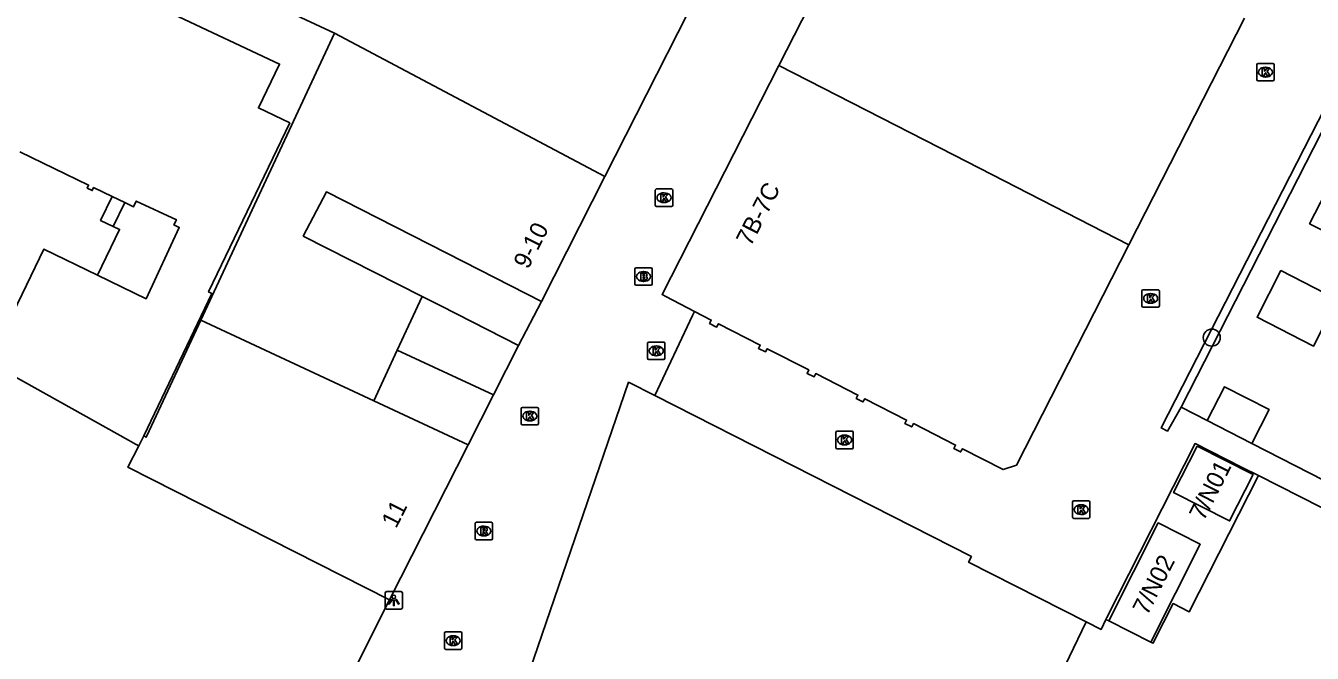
# Model space of a CAD drawing. Extents: x 160356 to 161355, y 381727 to 382845.
# Drawn here: x 160622.2 to 160696, y 382251.7 to 382287.6 of the extents above; entities that cross this region are included whole.
import ezdxf

# ---------------------------------------------------------------- set-up
doc = ezdxf.new("R2010")
doc.units = 0
for name, color, linetype in [('IMGEO_Boom', 7, 'Continuous'), ('IMGEO_Brandkraan', 7, 'Continuous'), ('IMGEO_Haag', 7, 'Continuous'), ('IMGEO_Kolk', 7, 'Continuous'), ('IMGEO_Lichtpunt', 7, 'Continuous'), ('IMGEO_Pand', 7, 'Continuous'), ('IMGEO_Pand_nummerreeks', 7, 'Continuous'), ('IMGEO_Rijbaan_lokaal_open', 7, 'Continuous'), ('IMGEO_Rioolput', 7, 'Continuous'), ('IMGEO_Voetpad_op_trap', 7, 'Continuous'), ('IMGEO_Voetpad_open', 7, 'Continuous')]:
    doc.layers.add(name, color=color, linetype=linetype)

msp = doc.modelspace()

# ---------------------------------------------------------------- linework, layer by layer
at = {"layer": 'IMGEO_Boom'}
msp.add_circle((160690.218, 382269.777), 0.489, dxfattribs=at)
at = {"layer": 'IMGEO_Brandkraan'}
for p, q in [((160657.122, 382272.853), (160657.122, 382273.705)), ((160657.197, 382273.779), (160658.049, 382273.779)), ((160657.61, 382273.559), (160657.635, 382273.559)), ((160658.123, 382273.705), (160658.123, 382272.853)), ((160658.049, 382272.779), (160657.197, 382272.779)), ((160657.633, 382272.999), (160657.608, 382272.999))]:
    msp.add_line(p, q, dxfattribs=at)
for points in [[(160657.122, 382272.853), (160657.122, 382273.705)], [(160657.197, 382273.779), (160658.049, 382273.779)], [(160657.47, 382273.479), (160657.47, 382273.079), (160657.683, 382273.079)], [(160657.701, 382273.479), (160657.47, 382273.479)], [(160658.123, 382273.705), (160658.123, 382272.853)], [(160658.049, 382272.779), (160657.197, 382272.779)], [(160657.649, 382273.398), (160657.595, 382273.398), (160657.595, 382273.322)], [(160657.595, 382273.322), (160657.648, 382273.322)], [(160657.657, 382273.246), (160657.595, 382273.246), (160657.595, 382273.165)], [(160657.595, 382273.165), (160657.657, 382273.165)]]:
    msp.add_lwpolyline(points, dxfattribs=at)
for centre, radius, start, end in [((160657.199, 382273.703), 0.0765, 91.55205, 178.44795), ((160657.199, 382273.703), 0.0765, 91.55205, 178.44795), ((160657.705, 382273.334), 0.145, 59.4692, 91.53667), ((160658.047, 382273.703), 0.0765, 1.55205, 88.44795), ((160658.047, 382273.703), 0.0765, 1.55205, 88.44795), ((160657.199, 382272.855), 0.0765, 181.55205, 268.44795), ((160657.199, 382272.855), 0.0765, 181.55205, 268.44795), ((160657.65, 382273.36), 0.0379, 267.82845, 90.93552), ((160657.658, 382273.205), 0.0404, 269.87594, 90.50774), ((160657.689, 382273.33), 0.251, 268.66757, 293.53466), ((160657.73, 382273.381), 0.0922, 285.51372, 58.15012), ((160657.735, 382273.189), 0.105, 301.31148, 78.98903), ((160658.047, 382272.855), 0.0765, 271.55205, 358.44795), ((160658.047, 382272.855), 0.0765, 271.55205, 358.44795)]:
    msp.add_arc(centre, radius, start, end, dxfattribs=at)
for centre, major_axis, ratio, start_param, end_param in [((160657.609, 382273.279), (-0.387, 0.002), 0.722429, 4.712389, 7.853982), ((160657.634, 382273.279), (-0.39, 0.002), 0.717154, 1.570796, 4.712389)]:
    msp.add_ellipse(centre, major_axis=major_axis, ratio=ratio, start_param=start_param, end_param=end_param, dxfattribs=at)
at = {"layer": 'IMGEO_Haag'}
msp.add_lwpolyline([(160688.461, 382265.787), (160729.098, 382345.248)], dxfattribs=at)
at = {"layer": 'IMGEO_Kolk'}
for p, q in [((160692.796, 382284.567), (160692.796, 382285.419)), ((160692.871, 382285.493), (160693.723, 382285.493)), ((160693.797, 382285.419), (160693.797, 382284.567)), ((160693.307, 382284.713), (160693.282, 382284.713)), ((160693.284, 382285.273), (160693.309, 382285.273)), ((160693.723, 382284.493), (160692.871, 382284.493)), ((160658.297, 382277.37), (160658.297, 382278.222)), ((160658.372, 382278.296), (160659.224, 382278.296)), ((160658.785, 382278.076), (160658.81, 382278.076)), ((160659.298, 382278.222), (160659.298, 382277.37)), ((160659.224, 382277.296), (160658.372, 382277.296)), ((160658.808, 382277.516), (160658.783, 382277.516)), ((160686.212, 382271.599), (160686.212, 382272.451)), ((160686.287, 382272.525), (160687.139, 382272.525)), ((160686.7, 382272.305), (160686.725, 382272.305)), ((160687.213, 382272.451), (160687.213, 382271.599)), ((160687.139, 382271.525), (160686.287, 382271.525)), ((160686.723, 382271.745), (160686.698, 382271.745)), ((160657.851, 382268.593), (160657.851, 382269.445)), ((160657.926, 382269.519), (160658.778, 382269.519)), ((160658.339, 382269.299), (160658.364, 382269.299)), ((160658.852, 382269.445), (160658.852, 382268.593)), ((160658.778, 382268.519), (160657.926, 382268.519)), ((160658.362, 382268.739), (160658.337, 382268.739)), ((160650.596, 382264.856), (160650.596, 382265.708)), ((160650.671, 382265.782), (160651.523, 382265.782)), ((160651.084, 382265.562), (160651.109, 382265.562)), ((160651.597, 382265.708), (160651.597, 382264.856)), ((160651.523, 382264.782), (160650.671, 382264.782)), ((160651.107, 382265.002), (160651.082, 382265.002)), ((160668.655, 382263.485), (160668.655, 382264.337)), ((160668.73, 382264.411), (160669.582, 382264.411)), ((160669.143, 382264.191), (160669.168, 382264.191)), ((160669.656, 382264.337), (160669.656, 382263.485)), ((160669.582, 382263.411), (160668.73, 382263.411)), ((160669.166, 382263.631), (160669.141, 382263.631)), ((160682.222, 382259.495), (160682.222, 382260.347)), ((160682.297, 382260.421), (160683.149, 382260.421)), ((160682.71, 382260.201), (160682.735, 382260.201)), ((160683.223, 382260.347), (160683.223, 382259.495)), ((160682.733, 382259.641), (160682.708, 382259.641)), ((160683.149, 382259.421), (160682.297, 382259.421)), ((160646.203, 382251.987), (160646.203, 382252.839)), ((160646.278, 382252.913), (160647.13, 382252.913)), ((160647.204, 382252.839), (160647.204, 382251.987)), ((160646.714, 382252.133), (160646.689, 382252.133)), ((160646.691, 382252.693), (160646.716, 382252.693)), ((160647.13, 382251.913), (160646.278, 382251.913))]:
    msp.add_line(p, q, dxfattribs=at)
for points in [[(160692.796, 382284.567), (160692.796, 382285.419)], [(160692.871, 382285.493), (160693.723, 382285.493)], [(160693.797, 382285.419), (160693.797, 382284.567)], [(160693.117, 382285.193), (160693.24, 382285.193), (160693.24, 382285.042), (160693.37, 382285.193), (160693.534, 382285.193), (160693.388, 382285.042), (160693.541, 382284.793), (160693.389, 382284.793), (160693.304, 382284.957), (160693.24, 382284.89), (160693.24, 382284.793), (160693.117, 382284.793), (160693.117, 382285.193)], [(160693.723, 382284.493), (160692.871, 382284.493)], [(160658.297, 382277.37), (160658.297, 382278.222)], [(160658.372, 382278.296), (160659.224, 382278.296)], [(160658.618, 382277.996), (160658.741, 382277.996), (160658.741, 382277.845), (160658.871, 382277.996), (160659.035, 382277.996), (160658.889, 382277.845), (160659.042, 382277.596), (160658.89, 382277.596), (160658.805, 382277.76), (160658.741, 382277.693), (160658.741, 382277.596), (160658.618, 382277.596), (160658.618, 382277.996)], [(160659.298, 382278.222), (160659.298, 382277.37)], [(160659.224, 382277.296), (160658.372, 382277.296)], [(160686.212, 382271.599), (160686.212, 382272.451)], [(160686.287, 382272.525), (160687.139, 382272.525)], [(160686.533, 382272.225), (160686.656, 382272.225), (160686.656, 382272.074), (160686.786, 382272.225), (160686.95, 382272.225), (160686.804, 382272.074), (160686.957, 382271.825), (160686.805, 382271.825), (160686.72, 382271.989), (160686.656, 382271.922), (160686.656, 382271.825), (160686.533, 382271.825), (160686.533, 382272.225)], [(160687.213, 382272.451), (160687.213, 382271.599)], [(160687.139, 382271.525), (160686.287, 382271.525)], [(160657.851, 382268.593), (160657.851, 382269.445)], [(160657.926, 382269.519), (160658.778, 382269.519)], [(160658.172, 382269.219), (160658.295, 382269.219), (160658.295, 382269.068), (160658.425, 382269.219), (160658.589, 382269.219), (160658.443, 382269.068), (160658.596, 382268.819), (160658.444, 382268.819), (160658.359, 382268.983), (160658.295, 382268.916), (160658.295, 382268.819), (160658.172, 382268.819), (160658.172, 382269.219)], [(160658.852, 382269.445), (160658.852, 382268.593)], [(160658.778, 382268.519), (160657.926, 382268.519)], [(160650.596, 382264.856), (160650.596, 382265.708)], [(160650.671, 382265.782), (160651.523, 382265.782)], [(160650.917, 382265.482), (160651.04, 382265.482), (160651.04, 382265.331), (160651.17, 382265.482), (160651.334, 382265.482), (160651.188, 382265.331), (160651.341, 382265.082), (160651.189, 382265.082), (160651.104, 382265.246), (160651.04, 382265.179), (160651.04, 382265.082), (160650.917, 382265.082), (160650.917, 382265.482)], [(160651.597, 382265.708), (160651.597, 382264.856)], [(160651.523, 382264.782), (160650.671, 382264.782)], [(160668.655, 382263.485), (160668.655, 382264.337)], [(160668.73, 382264.411), (160669.582, 382264.411)], [(160668.976, 382264.111), (160669.099, 382264.111), (160669.099, 382263.96), (160669.229, 382264.111), (160669.393, 382264.111), (160669.247, 382263.96), (160669.4, 382263.711), (160669.248, 382263.711), (160669.163, 382263.875), (160669.099, 382263.808), (160669.099, 382263.711), (160668.976, 382263.711), (160668.976, 382264.111)], [(160669.656, 382264.337), (160669.656, 382263.485)], [(160669.582, 382263.411), (160668.73, 382263.411)], [(160682.222, 382259.495), (160682.222, 382260.347)], [(160682.297, 382260.421), (160683.149, 382260.421)], [(160683.223, 382260.347), (160683.223, 382259.495)], [(160682.543, 382260.121), (160682.666, 382260.121), (160682.666, 382259.97), (160682.796, 382260.121), (160682.96, 382260.121), (160682.814, 382259.97), (160682.967, 382259.721), (160682.815, 382259.721), (160682.73, 382259.885), (160682.666, 382259.818), (160682.666, 382259.721), (160682.543, 382259.721), (160682.543, 382260.121)], [(160683.149, 382259.421), (160682.297, 382259.421)], [(160646.203, 382251.987), (160646.203, 382252.839)], [(160646.278, 382252.913), (160647.13, 382252.913)], [(160647.204, 382252.839), (160647.204, 382251.987)], [(160646.524, 382252.613), (160646.647, 382252.613), (160646.647, 382252.462), (160646.777, 382252.613), (160646.941, 382252.613), (160646.795, 382252.462), (160646.948, 382252.213), (160646.796, 382252.213), (160646.711, 382252.377), (160646.647, 382252.31), (160646.647, 382252.213), (160646.524, 382252.213), (160646.524, 382252.613)], [(160647.13, 382251.913), (160646.278, 382251.913)]]:
    msp.add_lwpolyline(points, dxfattribs=at)
for centre, start, end in [((160692.873, 382285.417), 91.55205, 178.44795), ((160692.873, 382285.417), 91.55205, 178.44795), ((160693.721, 382285.417), 1.55205, 88.44795), ((160693.721, 382285.417), 1.55205, 88.44795), ((160692.873, 382284.569), 181.55205, 268.44795), ((160692.873, 382284.569), 181.55205, 268.44795), ((160693.721, 382284.569), 271.55205, 358.44795), ((160693.721, 382284.569), 271.55205, 358.44795), ((160658.374, 382278.22), 91.55205, 178.44795), ((160658.374, 382278.22), 91.55205, 178.44795), ((160659.222, 382278.22), 1.55205, 88.44795), ((160659.222, 382278.22), 1.55205, 88.44795), ((160658.374, 382277.372), 181.55205, 268.44795), ((160658.374, 382277.372), 181.55205, 268.44795), ((160659.222, 382277.372), 271.55205, 358.44795), ((160659.222, 382277.372), 271.55205, 358.44795), ((160686.289, 382272.449), 91.55205, 178.44795), ((160686.289, 382272.449), 91.55205, 178.44795), ((160687.137, 382272.449), 1.55205, 88.44795), ((160687.137, 382272.449), 1.55205, 88.44795), ((160686.289, 382271.601), 181.55205, 268.44795), ((160686.289, 382271.601), 181.55205, 268.44795), ((160687.137, 382271.601), 271.55205, 358.44795), ((160687.137, 382271.601), 271.55205, 358.44795), ((160657.928, 382269.443), 91.55205, 178.44795), ((160657.928, 382269.443), 91.55205, 178.44795), ((160658.776, 382269.443), 1.55205, 88.44795), ((160658.776, 382269.443), 1.55205, 88.44795), ((160657.928, 382268.595), 181.55205, 268.44795), ((160657.928, 382268.595), 181.55205, 268.44795), ((160658.776, 382268.595), 271.55205, 358.44795), ((160658.776, 382268.595), 271.55205, 358.44795), ((160650.673, 382265.706), 91.55205, 178.44795), ((160650.673, 382265.706), 91.55205, 178.44795), ((160651.521, 382265.706), 1.55205, 88.44795), ((160651.521, 382265.706), 1.55205, 88.44795), ((160650.673, 382264.858), 181.55205, 268.44795), ((160650.673, 382264.858), 181.55205, 268.44795), ((160651.521, 382264.858), 271.55205, 358.44795), ((160651.521, 382264.858), 271.55205, 358.44795), ((160668.732, 382264.335), 91.55205, 178.44795), ((160668.732, 382264.335), 91.55205, 178.44795), ((160669.58, 382264.335), 1.55205, 88.44795), ((160669.58, 382264.335), 1.55205, 88.44795), ((160668.732, 382263.487), 181.55205, 268.44795), ((160668.732, 382263.487), 181.55205, 268.44795), ((160669.58, 382263.487), 271.55205, 358.44795), ((160669.58, 382263.487), 271.55205, 358.44795), ((160682.299, 382260.345), 91.55205, 178.44795), ((160682.299, 382260.345), 91.55205, 178.44795), ((160683.147, 382260.345), 1.55205, 88.44795), ((160683.147, 382260.345), 1.55205, 88.44795), ((160682.299, 382259.497), 181.55205, 268.44795), ((160682.299, 382259.497), 181.55205, 268.44795), ((160683.147, 382259.497), 271.55205, 358.44795), ((160683.147, 382259.497), 271.55205, 358.44795), ((160646.28, 382252.837), 91.55205, 178.44795), ((160646.28, 382252.837), 91.55205, 178.44795), ((160647.128, 382252.837), 1.55205, 88.44795), ((160647.128, 382252.837), 1.55205, 88.44795), ((160646.28, 382251.989), 181.55205, 268.44795), ((160646.28, 382251.989), 181.55205, 268.44795), ((160647.128, 382251.989), 271.55205, 358.44795), ((160647.128, 382251.989), 271.55205, 358.44795)]:
    msp.add_arc(centre, 0.0765, start, end, dxfattribs=at)
for centre, major_axis, ratio, start_param, end_param in [((160693.283, 382284.993), (-0.387, 0.002), 0.722429, 4.712389, 7.853982), ((160693.308, 382284.993), (-0.39, 0.002), 0.717154, 1.570796, 4.712389), ((160658.784, 382277.796), (-0.387, 0.002), 0.722429, 4.712389, 7.853982), ((160658.809, 382277.796), (-0.39, 0.002), 0.717154, 1.570796, 4.712389), ((160686.699, 382272.025), (-0.387, 0.002), 0.722429, 4.712389, 7.853982), ((160686.724, 382272.025), (-0.39, 0.002), 0.717154, 1.570796, 4.712389), ((160658.338, 382269.019), (-0.387, 0.002), 0.722429, 4.712389, 7.853982), ((160658.363, 382269.019), (-0.39, 0.002), 0.717154, 1.570796, 4.712389), ((160651.083, 382265.282), (-0.387, 0.002), 0.722429, 4.712389, 7.853982), ((160651.108, 382265.282), (-0.39, 0.002), 0.717154, 1.570796, 4.712389), ((160669.142, 382263.911), (-0.387, 0.002), 0.722429, 4.712389, 7.853982), ((160669.167, 382263.911), (-0.39, 0.002), 0.717154, 1.570796, 4.712389), ((160682.709, 382259.921), (-0.387, 0.002), 0.722429, 4.712389, 7.853982), ((160682.734, 382259.921), (-0.39, 0.002), 0.717154, 1.570796, 4.712389), ((160646.69, 382252.413), (-0.387, 0.002), 0.722429, 4.712389, 7.853982), ((160646.715, 382252.413), (-0.39, 0.002), 0.717154, 1.570796, 4.712389)]:
    msp.add_ellipse(centre, major_axis=major_axis, ratio=ratio, start_param=start_param, end_param=end_param, dxfattribs=at)
at = {"layer": 'IMGEO_Lichtpunt'}
for p, q in [((160642.801, 382255.127), (160642.801, 382254.32)), ((160642.801, 382255.127), (160642.801, 382254.32)), ((160643.703, 382255.222), (160642.895, 382255.222)), ((160643.703, 382255.222), (160642.895, 382255.222)), ((160643.797, 382254.32), (160643.797, 382255.127)), ((160643.797, 382254.32), (160643.797, 382255.127)), ((160642.895, 382254.226), (160643.703, 382254.226)), ((160642.895, 382254.226), (160643.703, 382254.226))]:
    msp.add_line(p, q, dxfattribs=at)
for points in [[(160643.175, 382254.791), (160643.214, 382254.763), (160643.026, 382254.501), (160642.988, 382254.528), (160643.175, 382254.791)], [(160643.277, 382254.743), (160643.324, 382254.743), (160643.324, 382254.421), (160643.277, 382254.421), (160643.277, 382254.743)], [(160643.387, 382254.763), (160643.425, 382254.79), (160643.612, 382254.528), (160643.573, 382254.5), (160643.387, 382254.763)]]:
    msp.add_lwpolyline(points, dxfattribs=at)
msp.add_circle((160643.3, 382254.925), 0.0994, dxfattribs=at)
for centre, start, end in [((160642.895, 382255.127), 90, 180), ((160642.895, 382255.127), 90, 180), ((160643.703, 382255.127), 0, 90), ((160643.703, 382255.127), 0, 90), ((160642.895, 382254.32), 180, 270), ((160642.895, 382254.32), 180, 270), ((160643.703, 382254.32), 270, 0), ((160643.703, 382254.32), 270, 360)]:
    msp.add_arc(centre, 0.0946, start, end, dxfattribs=at)
at = {"layer": 'IMGEO_Pand'}
for points in [[(160628.955, 382264.141), (160632.865, 382272.306), (160632.67, 382272.4), (160637.325, 382282.078), (160635.529, 382282.942), (160636.742, 382285.453), (160600.114, 382302.653)], [(160665.393, 382285.374), (160672.027, 382298.356)], [(160664.391, 382296.677), (160660.19, 382288.413), (160655.407, 382279.006)], [(160625.056, 382294.138), (160639.886, 382287.223)], [(160685.459, 382275.091), (160692.089, 382288.076)], [(160639.886, 382287.223), (160636.369, 382279.681), (160635.163, 382277.094), (160632.219, 382270.779)], [(160639.886, 382287.223), (160655.407, 382279.006)], [(160660.552, 382271.281), (160658.906, 382272.136), (160658.687, 382272.249), (160665.393, 382285.374)], [(160665.393, 382285.374), (160675.437, 382280.227), (160685.459, 382275.091)], [(160701.606, 382280.315), (160698.845, 382274.793), (160695.829, 382276.302), (160698.662, 382281.786), (160701.606, 382280.315)], [(160621.852, 382280.417), (160625.79, 382278.518), (160625.708, 382278.346), (160625.996, 382278.208), (160626.078, 382278.379), (160627.14, 382277.869)], [(160655.407, 382279.006), (160651.77, 382271.852)], [(160644.93, 382272.13), (160638.106, 382275.598), (160639.431, 382278.124), (160647.313, 382274.118), (160651.77, 382271.852)], [(160626.298, 382273.351), (160629.083, 382272.008), (160630.985, 382276.098), (160630.685, 382276.237), (160630.825, 382276.536), (160628.525, 382277.605), (160628.368, 382277.278), (160627.864, 382277.521)], [(160627.864, 382277.521), (160627.14, 382277.869)], [(160660.552, 382271.281), (160661.509, 382270.784), (160661.411, 382270.588), (160661.814, 382270.386), (160661.923, 382270.575), (160664.314, 382269.354), (160664.215, 382269.158), (160664.614, 382268.958), (160664.717, 382269.144), (160667.102, 382267.926), (160667.004, 382267.729), (160667.408, 382267.53), (160667.503, 382267.717), (160669.924, 382266.487), (160669.824, 382266.291), (160670.211, 382266.094), (160670.317, 382266.275), (160672.716, 382265.052), (160672.619, 382264.855), (160673.01, 382264.663), (160673.11, 382264.849), (160675.518, 382263.624), (160675.419, 382263.428), (160675.81, 382263.231), (160675.921, 382263.414), (160678.252, 382262.217), (160679.013, 382262.468), (160685.459, 382275.091)], [(160626.298, 382273.351), (160623.212, 382274.839), (160620.207, 382268.622), (160620.078, 382268.352)], [(160697.421, 382271.962), (160696.049, 382269.287), (160692.817, 382270.945), (160694.189, 382273.62), (160697.421, 382271.962)], [(160643.497, 382269.058), (160644.93, 382272.13)], [(160644.93, 382272.13), (160645.988, 382271.592), (160650.445, 382269.326)], [(160632.219, 382270.779), (160629.265, 382264.444), (160629.092, 382264.073), (160628.955, 382264.141)], [(160642.143, 382266.152), (160632.219, 382270.779)], [(160642.143, 382266.152), (160643.497, 382269.058)], [(160649.013, 382266.499), (160643.497, 382269.058)], [(160650.445, 382269.326), (160649.013, 382266.499)], [(160628.666, 382263.571), (160628.475, 382263.678), (160628.076, 382263.899), (160620.078, 382268.352)], [(160649.821, 382247), (160650.851, 382250), (160656.765, 382267.218), (160658.261, 382266.458)], [(160689.96, 382265.021), (160690.958, 382266.967), (160693.503, 382265.661), (160692.508, 382263.72)], [(160647.558, 382263.627), (160642.143, 382266.152)], [(160649.013, 382266.499), (160647.558, 382263.627)], [(160683.018, 382253.486), (160676.269, 382256.914), (160676.429, 382257.23), (160658.261, 382266.458)], [(160689.96, 382265.021), (160692.508, 382263.72)], [(160628.955, 382264.141), (160628.845, 382263.924), (160628.666, 382263.571)], [(160643.057, 382254.744), (160628.047, 382262.35), (160628.666, 382263.571)], [(160647.558, 382263.627), (160643.057, 382254.744)], [(160689.38, 382263.565), (160688.032, 382260.898), (160691.245, 382259.274), (160692.593, 382261.941), (160689.38, 382263.565)], [(160686.725, 382252.326), (160686.849, 382252.263), (160686.9, 382252.364), (160688.003, 382254.536), (160688.927, 382254.066), (160692.896, 382261.88)], [(160708.671, 382253.648), (160707.107, 382254.442), (160707.196, 382254.617), (160692.896, 382261.88)], [(160686.725, 382252.326), (160689.562, 382257.94), (160687.152, 382259.158), (160684.315, 382253.544)], [(160636.978, 382243.724), (160637.372, 382243.524), (160640.653, 382250), (160643.057, 382254.744)], [(160684.148, 382253.629), (160683.865, 382253.056), (160683.018, 382253.486)], [(160684.148, 382253.629), (160684.315, 382253.544)], [(160683.018, 382253.486), (160681.335, 382250), (160678.823, 382244.8)], [(160684.315, 382253.544), (160686.725, 382252.326)]]:
    msp.add_lwpolyline(points, dxfattribs=at)
at = {"layer": 'IMGEO_Rijbaan_lokaal_open'}
for points in [[(160627.14, 382277.869), (160626.479, 382276.499), (160627.203, 382276.15)], [(160627.203, 382276.15), (160627.563, 382275.976), (160626.298, 382273.351)], [(160651.77, 382271.852), (160650.445, 382269.326)], [(160658.261, 382266.458), (160660.439, 382271.044), (160660.552, 382271.281)]]:
    msp.add_lwpolyline(points, dxfattribs=at)
at = {"layer": 'IMGEO_Rioolput'}
for p, q in [((160647.961, 382258.268), (160647.961, 382259.12)), ((160648.036, 382259.194), (160648.888, 382259.194)), ((160648.449, 382258.974), (160648.474, 382258.974)), ((160648.962, 382259.12), (160648.962, 382258.268)), ((160648.888, 382258.194), (160648.036, 382258.194)), ((160648.472, 382258.414), (160648.447, 382258.414))]:
    msp.add_line(p, q, dxfattribs=at)
for points in [[(160647.961, 382258.268), (160647.961, 382259.12)], [(160648.036, 382259.194), (160648.888, 382259.194)], [(160648.55, 382258.892), (160648.298, 382258.894), (160648.298, 382258.494)], [(160648.476, 382258.813), (160648.422, 382258.813), (160648.422, 382258.732)], [(160648.422, 382258.732), (160648.474, 382258.732)], [(160648.962, 382259.12), (160648.962, 382258.268)], [(160648.888, 382258.194), (160648.036, 382258.194)], [(160648.298, 382258.494), (160648.422, 382258.494), (160648.422, 382258.656), (160648.433, 382258.656)], [(160648.48, 382258.627), (160648.551, 382258.494), (160648.691, 382258.494), (160648.626, 382258.62)]]:
    msp.add_lwpolyline(points, dxfattribs=at)
for centre, radius, start, end in [((160648.038, 382259.118), 0.0765, 91.55205, 178.44795), ((160648.038, 382259.118), 0.0765, 91.55205, 178.44795), ((160648.458, 382258.921), 0.19, 274.7715, 282.96867), ((160648.482, 382258.717), 0.0964, 77.00612, 93.18647), ((160648.496, 382258.774), 0.0378, 276.66336, 79.67722), ((160648.549, 382258.782), 0.109, 350.36119, 89.41601), ((160648.547, 382258.782), 0.112, 277.58423, 350.98172), ((160648.886, 382259.118), 0.0765, 1.55205, 88.44795), ((160648.886, 382259.118), 0.0765, 1.55205, 88.44795), ((160648.038, 382258.27), 0.0765, 181.55205, 268.44795), ((160648.038, 382258.27), 0.0765, 181.55205, 268.44795), ((160648.432, 382258.603), 0.0533, 26.02933, 88.69889), ((160648.531, 382258.567), 0.108, 29.51342, 73.79051), ((160648.886, 382258.27), 0.0765, 271.55205, 358.44795), ((160648.886, 382258.27), 0.0765, 271.55205, 358.44795)]:
    msp.add_arc(centre, radius, start, end, dxfattribs=at)
for centre, major_axis, ratio, start_param, end_param in [((160648.448, 382258.694), (-0.387, 0.002), 0.722429, 4.712389, 7.853982), ((160648.473, 382258.694), (-0.39, 0.002), 0.717154, 1.570796, 4.712389)]:
    msp.add_ellipse(centre, major_axis=major_axis, ratio=ratio, start_param=start_param, end_param=end_param, dxfattribs=at)
at = {"layer": 'IMGEO_Voetpad_op_trap'}
msp.add_lwpolyline([(160627.203, 382276.15), (160627.864, 382277.521)], dxfattribs=at)
at = {"layer": 'IMGEO_Voetpad_open'}
for points in [[(160735.595, 382357.997), (160735.246, 382358.167), (160687.321, 382264.602), (160687.672, 382264.425), (160688.461, 382265.787)], [(160688.461, 382265.787), (160689.96, 382265.021)], [(160692.896, 382261.88), (160691.963, 382262.334), (160689.263, 382263.706), (160684.2, 382253.735), (160684.148, 382253.629)], [(160692.508, 382263.72), (160699.952, 382259.918)]]:
    msp.add_lwpolyline(points, dxfattribs=at)

# ---------------------------------------------------------------- texts
at = {"layer": 'IMGEO_Pand_nummerreeks'}
for s, rotation, p in [('7B-7C', 62.91937, (160663.77, 382274.958)), ('9-10', 63.05401, (160651.002, 382273.651)), ('7/N01', 63.08838, (160689.76, 382259.227)), ('11', 63.12849, (160643.429, 382258.799)), ('7/N02', 63.09411, (160686.517, 382253.809))]:
    msp.add_text(s, height=1, rotation=rotation, dxfattribs=at).set_placement(p)

doc.saveas('drawing.dxf')
